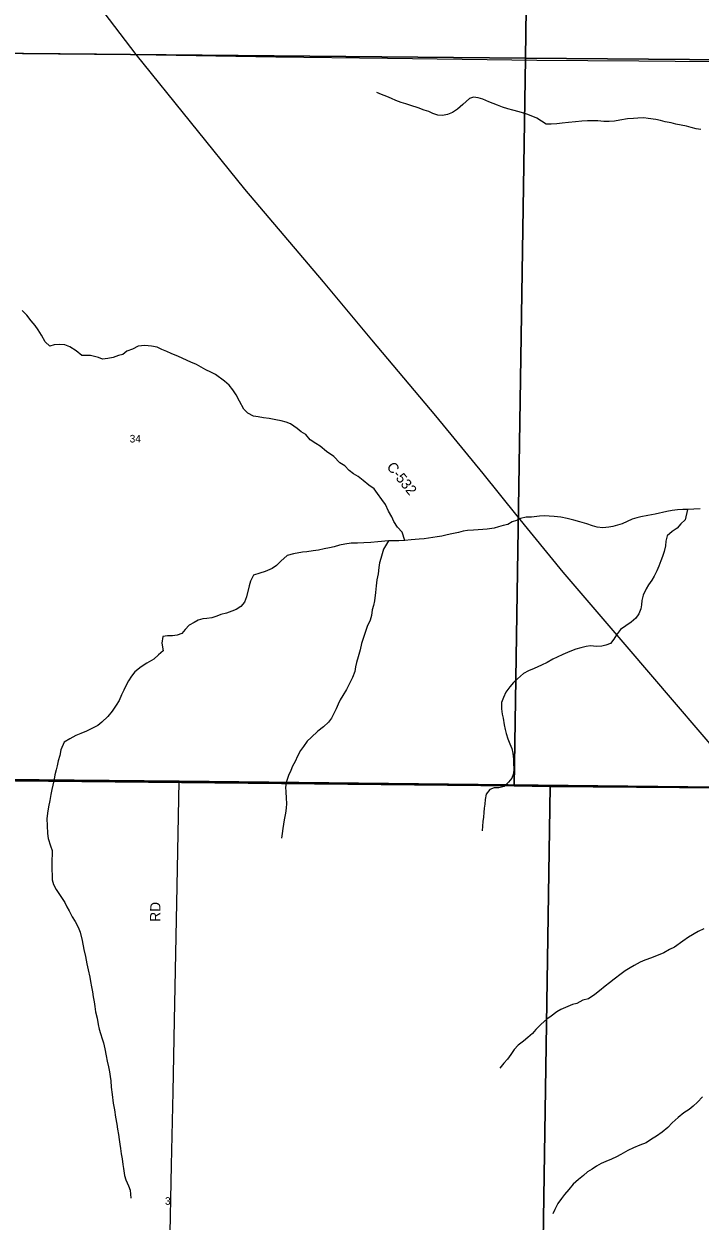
# Model space of a CAD drawing. Extents: x 1312308 to 1684953, y 460642 to 865172.
# Drawn here: x 1428928 to 1433853, y 606234 to 614954 of the extents above; entities that cross this region are included whole.
import ezdxf

# ---------------------------------------------------------------- set-up
doc = ezdxf.new("R2010")
doc.units = 0
for name, color, linetype in [('GM_X_County_Road', 7, 'Continuous'), ('GM_X_County_Road_Text', 7, 'Continuous'), ('GM_X_Minor_River', 7, 'Continuous'), ('GM_X_Section', 7, 'Continuous'), ('GM_X_Section_Text', 7, 'Continuous'), ('GM_X_Township', 7, 'Continuous'), ('GM_X_Township_Road', 7, 'Continuous'), ('GM_X_Township_Road_Text', 7, 'Continuous')]:
    doc.layers.add(name, color=color, linetype=linetype)

msp = doc.modelspace()

# ---------------------------------------------------------------- linework, layer by layer
at = {"layer": 'GM_X_County_Road'}
for points in [[(1434197.2, 609392.5), (1433321.1, 610416.1), (1432855.2, 610960.9), (1432519.8, 611370.7), (1432273.9, 611680.1), (1431928.4, 612099), (1431461.6, 612653.5), (1431109.8, 613075.1), (1430537.7, 613750.3), (1429745.8, 614732.5), (1429325.1, 615284.2), (1429124.3, 615518.8), (1428892, 615774.3), (1428690.9, 615972.9), (1428138.6, 616505.8), (1427967.9, 616667.8), (1427961, 616674.7)], [(1427089.2, 614759.2), (1427860.7, 614750.1), (1429455.8, 614735.5), (1429745.8, 614732.5)], [(1429745.8, 614732.5), (1430763.3, 614714.5), (1431576.4, 614704.1), (1432664.2, 614691), (1433406.6, 614684.8), (1434467.6, 614675.8), (1435106.2, 614671.9)], [(1427248.1, 609464.9), (1427248.1, 609464.9), (1430057.8, 609437.8), (1434197.2, 609392.5)]]:
    msp.add_lwpolyline(points, dxfattribs=at)
at = {"layer": 'GM_X_Minor_River'}
for points in [[(1432344.6, 614373.5), (1432314.7, 614386.1), (1432271, 614405), (1432237.1, 614415.7), (1432203.1, 614420.3), (1432172.8, 614410.9), (1432125.8, 614367.6), (1432087, 614332.2), (1432050.4, 614308.8), (1432012, 614293.4), (1431977.8, 614288), (1431943.7, 614288.7), (1431905.8, 614301.4), (1431876, 614316), (1431842.2, 614326.7), (1431800.4, 614343.5), (1431746.6, 614360.6), (1431708.7, 614371.3), (1431674.8, 614382), (1431637, 614396.8), (1431605.2, 614411.4), (1431571.4, 614426.1), (1431531.6, 614440.9), (1431497.8, 614453.6)], [(1433859.1, 614184.8), (1433825.1, 614189.4), (1433787.2, 614200.2), (1433753.2, 614208.8), (1433715.3, 614217.6), (1433677.3, 614224.3), (1433641.4, 614233), (1433599.5, 614241.8), (1433565.6, 614250.5), (1433531.6, 614257.1), (1433473.6, 614266.2), (1433443.6, 614268.8), (1433399.4, 614267.6), (1433367.3, 614266.2), (1433325.1, 614263), (1433268.7, 614252), (1433230.5, 614246.7), (1433190.3, 614243.4), (1433152.2, 614244.1), (1433108.2, 614246.9), (1433034, 614248.3), (1432991.8, 614245.1), (1432945.6, 614241.9), (1432895.4, 614236.8), (1432849.1, 614231.7), (1432808.9, 614226.4), (1432768.7, 614223.1), (1432730.6, 614223.8), (1432697, 614246.5), (1432663.3, 614267.2), (1432633.5, 614279.8), (1432589.7, 614296.7), (1432533.9, 614313.8), (1432488, 614324.7), (1432452.1, 614335.4), (1432414.2, 614348.2), (1432376.4, 614362.9), (1432344.6, 614373.5)], [(1431701.7, 611190.5), (1431682.9, 611253), (1431649.5, 611287.8), (1431622.3, 611330.4), (1431607, 611364.8), (1431583.7, 611405.4), (1431560.7, 611454), (1431535.3, 611490.6), (1431504.1, 611533.3), (1431478.7, 611567.9), (1431439.2, 611594.7), (1431397.7, 611627.6), (1431362.3, 611658.3), (1431328.5, 611677), (1431297, 611701.7), (1431265.5, 611734.4), (1431227.9, 611757.1), (1431184.7, 611804.1), (1431131.3, 611839.2), (1431086, 611878.2), (1431054.3, 611898.8), (1431012.7, 611925.7), (1430981.4, 611962.4), (1430947.7, 611983.1), (1430918.1, 612007.7), (1430868.6, 612040.8), (1430836.8, 612053.4), (1430800.9, 612064.1), (1430763, 612070.8), (1430715, 612079.7), (1430673, 612084.5), (1430633, 612091.3), (1430599, 612097.9), (1430559.4, 612118.8), (1430529.9, 612147.4), (1430499, 612206.2), (1430473.8, 612252.8), (1430448.5, 612289.4), (1430423.1, 612322), (1430389.6, 612350.7), (1430322.4, 612400.1), (1430288.7, 612416.8), (1430252.9, 612435.5), (1430219.2, 612454.2), (1430183.5, 612472.9), (1430143.7, 612489.7), (1430054.3, 612531.5), (1430000.6, 612552.6), (1429968.8, 612567.3), (1429931, 612582), (1429897.3, 612600.7), (1429857.3, 612607.5), (1429807.3, 612612.4), (1429761, 612607.2), (1429718.4, 612584), (1429678.1, 612570.7), (1429647.5, 612547.2), (1429617.2, 612537.7), (1429576.8, 612524.4), (1429538.5, 612517.1), (1429500.3, 612511.8), (1429470.5, 612524.4), (1429412.6, 612539.5), (1429380.5, 612538.1), (1429350.5, 612538.7), (1429307, 612571.6), (1429261.5, 612602.5), (1429225.7, 612617.2), (1429183.6, 612620), (1429147.5, 612616.7), (1429115.2, 612607.3), (1429081.7, 612638), (1429054.6, 612686.7), (1429031.3, 612725.2), (1429009.9, 612757.7), (1428980.5, 612790.4), (1428949.3, 612833.1), (1428913.9, 612865.9)], [(1433762.2, 611417.1), (1433744.6, 611341.2), (1433711.9, 611311.7), (1433685.2, 611282.1), (1433650.6, 611256.7), (1433613.9, 611225.2), (1433603.1, 611187.3), (1433600.3, 611151.2), (1433591.5, 611111.3), (1433578.7, 611075.4), (1433568, 611043.5), (1433553.2, 611003.7), (1433538.5, 610969.8), (1433517.6, 610932.1), (1433501, 610902.3), (1433478.2, 610868.6), (1433459.5, 610838.8), (1433438.6, 610793.1), (1433427.7, 610755.2), (1433425.1, 610723.1), (1433420.5, 610693.1), (1433405.7, 610657.3), (1433385, 610625.5), (1433350.3, 610596.1), (1433311.6, 610570.7), (1433273, 610543.3), (1433244.1, 610503.8), (1433225.4, 610472), (1433200.7, 610440.3), (1433166.3, 610429), (1433136.1, 610421.5), (1433098, 610420.2), (1433053.9, 610423), (1433023.7, 610419.6), (1432985.4, 610410.2), (1432947.1, 610398.9), (1432904.7, 610383.6), (1432852, 610360.5), (1432811.5, 610341.2), (1432781.1, 610325.7), (1432738.5, 610302.4), (1432698, 610283.1), (1432645.4, 610260), (1432602.9, 610242.8), (1432566.4, 610223.4), (1432523.5, 610184), (1432492.8, 610156.5), (1432466.1, 610124.9), (1432437.2, 610085.3), (1432420.4, 610047.5), (1432405.6, 610011.7), (1432406.7, 609965.5), (1432411.9, 609927.3), (1432417.3, 609897.1), (1432426.4, 609848.8), (1432433.7, 609814.5), (1432441.1, 609784.3), (1432452.3, 609746), (1432467.6, 609709.6), (1432481, 609675.2), (1432488.3, 609641), (1432493.4, 609598.8), (1432494.8, 609568.6), (1432496, 609528.5), (1432493.3, 609494.4), (1432480.6, 609460.5), (1432457.9, 609430.9), (1432425.2, 609399.4), (1432386.9, 609390.1), (1432352.7, 609388.7), (1432322.4, 609377.2), (1432295.7, 609343.6), (1432286.8, 609303.6), (1432284.2, 609271.6), (1432279.5, 609241.6), (1432276.9, 609209.5), (1432274.2, 609175.5), (1432271.5, 609145.4), (1432268.8, 609109.4), (1432266.1, 609075.3)], [(1433854.6, 611421.4), (1433806.4, 611418.3), (1433762.2, 611417.1), (1433728.1, 611417.8), (1433688, 611414.5), (1433649.7, 611409.2), (1433611.5, 611401.9), (1433526.9, 611383.4), (1433472.5, 611374.3), (1433422.2, 611363.2), (1433391.9, 611355.8), (1433357.6, 611346.4), (1433321.2, 611329), (1433284.7, 611313.6), (1433218.1, 611292.8), (1433187.9, 611287.3), (1433145.7, 611284.1), (1433103.7, 611288.9), (1433069.8, 611297.5), (1433028, 611312.4), (1432976.1, 611327.4), (1432934.3, 611340.2), (1432884.4, 611351.1), (1432838.4, 611360), (1432790.4, 611364.9), (1432754.4, 611369.6), (1432716.3, 611370.3), (1432684.1, 611368.9), (1432623.8, 611362), (1432585.7, 611360.7), (1432545.4, 611351.4), (1432515, 611337.9)], [(1432515, 611337.9), (1432484.7, 611326.4), (1432452.2, 611307), (1432418, 611299.6), (1432383.7, 611290.2), (1432353.4, 611280.7), (1432301.1, 611273.7), (1432270.9, 611270.2), (1432202.7, 611267.5), (1432158.5, 611264.3), (1432128.3, 611258.8), (1432092, 611249.5), (1432045.7, 611240.3), (1432009.4, 611232.9), (1431971.1, 611223.6), (1431938.9, 611218.2), (1431842.4, 611203.9), (1431806.2, 611200.6), (1431747.9, 611195.7), (1431701.7, 611190.5), (1431659.5, 611189.3), (1431629.4, 611187.8), (1431583.3, 611188.7), (1431504.9, 611182.1), (1431454.7, 611177), (1431404.5, 611173.9), (1431358.3, 611172.8), (1431312.2, 611171.7), (1431265.9, 611164.5), (1431225.6, 611157.2), (1431187.3, 611145.9), (1431153, 611138.5), (1431114.8, 611131.2), (1431074.5, 611121.9), (1431034.2, 611116.6), (1430988, 611109.4), (1430955.8, 611106), (1430891.4, 611093.2), (1430845, 611082), (1430800, 611040.7), (1430767.3, 611009.2), (1430736.8, 610987.7), (1430684.2, 610966.6), (1430645.8, 610953.3), (1430599.4, 610938.1), (1430578.4, 610894.3), (1430567.7, 610860.4), (1430550, 610780.5), (1430533.2, 610742.7), (1430506.5, 610711.1), (1430473.9, 610689.6), (1430441.5, 610676.2), (1430403.2, 610662.8), (1430362.8, 610651.5), (1430332.5, 610640.1), (1430296.2, 610628.7), (1430260, 610623.3), (1430229.8, 610619.9), (1430197.5, 610610.5), (1430167.1, 610593), (1430130.6, 610573.6), (1430101.9, 610544), (1430077.2, 610514.4), (1430044.8, 610500.9), (1430010.7, 610497.6), (1429974.5, 610496.2), (1429940.3, 610490.8), (1429931.3, 610442.8), (1429942.2, 610386.5), (1429907.5, 610359), (1429874.8, 610327.5), (1429824.1, 610298.4), (1429781.4, 610271.1), (1429736.5, 610235.8), (1429711.8, 610202.1), (1429689, 610168.5), (1429672.3, 610136.7), (1429655.5, 610100.9), (1429638.8, 610067.1), (1429621.9, 610025.2), (1429599.1, 609991.5), (1429570.2, 609947.9), (1429539.3, 609908.4), (1429496.3, 609867.1), (1429465.7, 609843.5), (1429431.3, 609826.1), (1429382.7, 609803), (1429342.2, 609785.7), (1429305.8, 609770.3), (1429263.2, 609747), (1429220.5, 609721.7), (1429195.3, 609666), (1429188.5, 609626), (1429177.6, 609586.1), (1429168.9, 609550.1), (1429162.3, 609520.1), (1429153.5, 609484.2), (1429146.8, 609452.2), (1429137.9, 609408.2), (1429131.3, 609378.3), (1429122.5, 609342.3)], [(1431583.3, 611188.7), (1431547.9, 611127.1), (1431526.5, 611059.3), (1431517.8, 611027.4), (1431513.1, 610995.3), (1431508.2, 610949.3), (1431499.3, 610905.3), (1431494.4, 610861.2), (1431489.4, 610813.2), (1431480.1, 610751.2), (1431473.4, 610717.2), (1431464.7, 610687.2), (1431459.8, 610645.2), (1431449.1, 610611.3), (1431428.1, 610565.5), (1431398.2, 610477.8), (1431387.5, 610441.9), (1431376.5, 610395.9), (1431361.4, 610344), (1431350.5, 610302.1), (1431343.9, 610272.1), (1431337.1, 610236.2), (1431322.2, 610192.3), (1431299.2, 610148.6), (1431276.3, 610106.9), (1431251.4, 610063.2), (1431230.6, 610029.5), (1431216, 609999.6), (1431201.2, 609965.8), (1431167.7, 609898.2), (1431147.1, 609868.5), (1431110.3, 609835.1), (1431069.5, 609801.7), (1431020.4, 609756.5), (1430989.8, 609728.9), (1430962.9, 609691.3), (1430942.3, 609661.6), (1430919.4, 609619.9), (1430902.5, 609582.1), (1430883.7, 609546.3), (1430871.1, 609516.5), (1430854.3, 609478.7), (1430839.4, 609436.8), (1430832.5, 609394.8), (1430835.8, 609360.6), (1430838.9, 609314.4), (1430840.1, 609276.3), (1430837.4, 609242.2), (1430832.6, 609204.2), (1430823.6, 609156.2), (1430818.9, 609124.2), (1430814.3, 609094.2), (1430807.6, 609058.2), (1430804.9, 609024.2)], [(1429122.5, 609342.3), (1429115.6, 609298.3), (1429106.6, 609250.3), (1429099.6, 609204.3), (1429094.8, 609164.2), (1429095.8, 609116.1), (1429098.6, 609057.8), (1429103.9, 609019.6), (1429120.8, 608967.1), (1429132.2, 608932.8), (1429130.2, 608836.5), (1429131.3, 608790.4), (1429132.6, 608756.2), (1429133.8, 608720.1), (1429143.2, 608685.8), (1429162.5, 608649.4), (1429205.3, 608584.4), (1429224.7, 608553.9), (1429240.1, 608523.5), (1429257.6, 608493.1), (1429278.7, 608450.6), (1429302.1, 608416), (1429323.3, 608375.5), (1429336.6, 608339.2), (1429351.4, 608278.7), (1429364.1, 608212.2), (1429375.1, 608161.9), (1429386.1, 608107.5), (1429395.2, 608063.2), (1429408.1, 608010.8), (1429413.5, 607978.6), (1429418.7, 607940.4), (1429426, 607904.1), (1429431.3, 607867.9), (1429438.5, 607829.7), (1429443.9, 607797.5), (1429449.1, 607757.2), (1429460.2, 607710.9), (1429469.3, 607666.6), (1429476.6, 607632.3), (1429486, 607600.1), (1429497.2, 607561.8), (1429506.6, 607531.5), (1429517.8, 607489.2), (1429526.8, 607436.8), (1429534, 607398.6), (1429543.2, 607356.3), (1429550.5, 607322), (1429555.8, 607285.8), (1429561.2, 607255.6), (1429564.2, 607209.4), (1429571.1, 607155.1), (1429577.9, 607092.8), (1429586.9, 607044.5), (1429593.8, 606990.2), (1429604.8, 606939.8), (1429610.1, 606903.6), (1429617.3, 606863.4), (1429620.6, 606829.2), (1429625.9, 606793), (1429631.3, 606762.8), (1429636.5, 606724.6), (1429643.8, 606688.3), (1429649, 606646.1), (1429652.4, 606615.9), (1429661.4, 606565.6), (1429668.8, 606535.4), (1429689.9, 606490.9), (1429701.3, 606458.5), (1429706.1, 606400.3)], [(1433880.2, 608363.3), (1433839.6, 608342), (1433768.6, 608301.2), (1433727.9, 608273.8), (1433666.8, 608228.8), (1433630.4, 608211.4), (1433589.8, 608188.1), (1433559.5, 608176.7), (1433529.1, 608163.2), (1433498.8, 608151.7), (1433450.3, 608134.5), (1433415.9, 608119.1), (1433373.3, 608095.8), (1433342.8, 608078.3), (1433308.3, 608056.9), (1433277.8, 608035.4), (1433226.8, 607996.2), (1433192.2, 607968.8), (1433161.6, 607945.3), (1433120.8, 607911.9), (1433086.1, 607884.5), (1433039.4, 607853.2), (1432999, 607841.9), (1432954.4, 607818.7), (1432924.2, 607811.2), (1432871.6, 607790.1), (1432839.2, 607774.7), (1432808.7, 607757.2), (1432768, 607725.8), (1432737.5, 607704.3), (1432694.6, 607669), (1432655.7, 607629.6), (1432633, 607599.9), (1432598.3, 607570.5), (1432565.7, 607545), (1432527, 607515.7), (1432498.3, 607484.1), (1432473.5, 607448.4), (1432450.7, 607412.7), (1432424, 607383.2), (1432393.2, 607347.6)], [(1433871.2, 607139.7), (1433834.3, 607100.3), (1433803.6, 607070.8), (1433773, 607047.2), (1433734.4, 607021.9)], [(1433734.4, 607021.9), (1433693.6, 606988.5), (1433650.7, 606949.2), (1433617.9, 606915.7), (1433577.1, 606882.3), (1433534.4, 606853), (1433499.8, 606829.6), (1433461.2, 606804.2), (1433414.7, 606787), (1433368.1, 606767.8), (1433327.6, 606748.5), (1433274.9, 606719.4), (1433244.4, 606701.9), (1433208, 606684.5), (1433165.5, 606667.3), (1433133.1, 606653.8), (1433098.6, 606634.4), (1433066.1, 606612.9), (1433033.6, 606591.5), (1433003, 606566), (1432968.3, 606536.5), (1432929.5, 606503.1), (1432896.6, 606463.6), (1432865.8, 606428.1), (1432843.1, 606398.4), (1432816.2, 606360.8), (1432795.3, 606319), (1432780.6, 606287.2)]]:
    msp.add_lwpolyline(points, dxfattribs=at)
at = {"layer": 'GM_X_Section'}
for points in [[(1426939.4, 619468.3), (1432643.4, 619381.8), (1432580.9, 614705.3), (1427084.1, 614755.3)], [(1432643.4, 619381.8), (1437545.7, 619310.6), (1437653.9, 614662.4), (1432580.9, 614705.3)], [(1432580.9, 614705.3), (1432499.1, 609405.2), (1427408.4, 609456.4), (1427288.4, 609459), (1427084.1, 614755.3)], [(1437653.9, 614662.4), (1437782, 609359.8), (1432761, 609399.6), (1432499.1, 609405.2), (1432580.9, 614705.3)], [(1427408.4, 609456.4), (1432499.1, 609405.2), (1432761, 609399.6), (1432672, 603575.6), (1427318.8, 603698.4)], [(1432761, 609399.6), (1437782, 609359.8), (1437889.9, 609357.5), (1437907.9, 603579.3), (1432672, 603575.6)]]:
    msp.add_lwpolyline(points, close=True, dxfattribs=at)
at = {"layer": 'GM_X_Township'}
for points in [[(1443487.4, 629689.1), (1443383.2, 625252.4), (1443279.1, 619936.6), (1443262.6, 619245.4), (1443164.3, 614625), (1443062.5, 609310), (1440472, 609335.1), (1437771.4, 609361.5), (1435199.7, 609380.4), (1434197.2, 609392.5), (1430057.8, 609437.8), (1427248.1, 609464.9), (1424759.1, 609498.2), (1422200.5, 609520.2), (1411036.3, 609617.7), (1410999.4, 609618.2), (1411017.8, 611981.1), (1411020.1, 612268.6), (1411090.2, 617032.9), (1411094.7, 617623.7), (1411153.4, 624951), (1411163.3, 625647.7), (1411180.4, 628296.4), (1411210.5, 633565.2)], [(1410955.4, 603991.6), (1410977, 606750.9), (1410982, 607392.1), (1410997.9, 609428.6), (1410999.4, 609618.2), (1411036.3, 609617.7), (1422200.5, 609520.2), (1424759.1, 609498.2), (1427248.1, 609464.9), (1430057.8, 609437.8), (1434197.2, 609392.5), (1435199.7, 609380.4), (1437771.4, 609361.5), (1440472, 609335.1), (1443062.5, 609310), (1445748.3, 609283.3), (1452218.2, 609194.8), (1453828.1, 609169), (1453803.6, 608986.7), (1453761.5, 603813.9)]]:
    msp.add_lwpolyline(points, dxfattribs=at)
at = {"layer": 'GM_X_Township_Road'}
msp.add_lwpolyline([(1432671.2, 604835.1), (1432485.9, 605010.5), (1432335.9, 605174.7), (1432276.6, 605202.3), (1431922.5, 605211.5), (1431410.2, 605216.8), (1430853.8, 605223.2), (1430377.6, 605229.6), (1430081.5, 605237.2), (1429991.8, 605253.6), (1429987.6, 605636.4), (1429991.6, 606024.9), (1430001.4, 606641.7), (1430015.1, 607176.3), (1430024.4, 607695), (1430043.5, 608674.2), (1430057.8, 609437.8)], dxfattribs=at)

# ---------------------------------------------------------------- texts
at = {"layer": 'GM_X_County_Road_Text'}
msp.add_text('C-532', height=75, rotation=309.04207, dxfattribs=at).set_placement((1431565.5, 611726))
at = {"layer": 'GM_X_Section_Text'}
for s, height, p in [('34', 55.25, (1429697.6, 611905.2)), ('3', 55.3, (1429955, 606352.4))]:
    msp.add_text(s, height=height, rotation=0.00001, dxfattribs=at).set_placement(p)
at = {"layer": 'GM_X_Township_Road_Text'}
msp.add_text('RD', height=75, rotation=89.0206, dxfattribs=at).set_placement((1429920.6, 608413.2))

doc.saveas('drawing.dxf')
